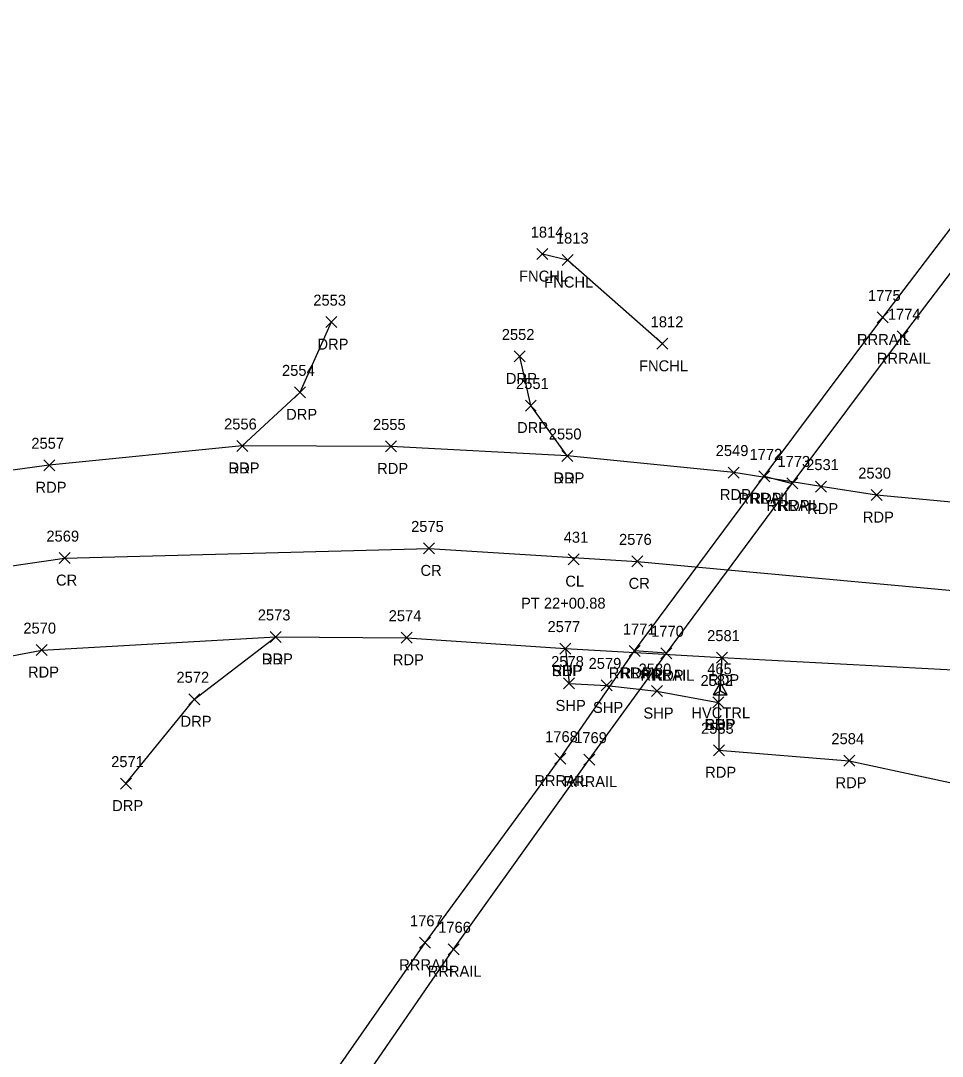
# Model space of a CAD drawing. Extents: x 1767353 to 1772625, y 740790 to 747702.
# Drawn here: x 1772120.9 to 1772288.6, y 747316.1 to 747504.6 of the extents above; entities that cross this region are included whole.
import ezdxf

# ---------------------------------------------------------------- set-up
doc = ezdxf.new("R2010")
doc.units = 0
for name, color, linetype in [('A_A', 7, 'Continuous'), ('A_C', 7, 'Continuous'), ('A_I', 7, 'Continuous'), ('A_TIC', 7, 'Continuous'), ('C_A', 7, 'Continuous'), ('C_I', 7, 'Continuous'), ('CPSM', 7, 'Continuous'), ('L_A', 7, 'Continuous'), ('L_I', 7, 'Continuous'), ('L_TIC', 7, 'Continuous'), ('LFNC', 7, 'Continuous'), ('P_A', 7, 'Continuous'), ('P_I', 7, 'Continuous'), ('P_TIC', 7, 'Continuous'), ('PET', 7, 'Continuous'), ('PRC', 7, 'Continuous'), ('PSP', 7, 'Continuous'), ('R_A', 7, 'Continuous'), ('R_I', 7, 'Continuous'), ('R_TIC', 7, 'Continuous'), ('RDP', 7, 'Continuous'), ('RR', 7, 'Continuous')]:
    doc.layers.add(name, color=color, linetype=linetype)

msp = doc.modelspace()

# ---------------------------------------------------------------- linework, layer by layer
at = {"layer": 'A_TIC'}
for points in [[(1772220.5, 747405.59), (1772222.5, 747407.59)], [(1772222.5, 747405.59), (1772220.5, 747407.59)]]:
    msp.add_lwpolyline(points, dxfattribs=at)
at = {"layer": 'CPSM'}
for p, q in [((1772246.97, 747381.92), (1772248.22, 747384.08)), ((1772249.47, 747381.92), (1772248.22, 747384.08)), ((1772248.22, 747382.64), (1772248.22, 747384.08)), ((1772246.97, 747381.92), (1772248.22, 747382.64)), ((1772246.97, 747381.92), (1772249.47, 747381.92)), ((1772248.22, 747382.64), (1772248.22, 747382.64)), ((1772248.22, 747382.64), (1772249.47, 747381.92))]:
    msp.add_line(p, q, dxfattribs=at)
at = {"layer": 'L_TIC'}
for points in [[(1772214.82, 747461.1), (1772216.82, 747463.1)], [(1772216.82, 747461.1), (1772214.82, 747463.1)], [(1772219.4, 747460.02), (1772221.4, 747462.02)], [(1772221.4, 747460.02), (1772219.4, 747462.02)], [(1772236.65, 747444.78), (1772238.65, 747446.78)], [(1772238.65, 747444.78), (1772236.65, 747446.78)]]:
    msp.add_lwpolyline(points, dxfattribs=at)
at = {"layer": 'LFNC'}
msp.add_lwpolyline([(1772237.65, 747445.78), (1772220.4, 747461.02), (1772215.82, 747462.1)], dxfattribs=at)
at = {"layer": 'P_TIC'}
for points in [[(1772160.2, 747426.19), (1772162.2, 747428.19)], [(1772162.2, 747426.19), (1772160.2, 747428.19)], [(1772187.24, 747426.11), (1772189.24, 747428.11)], [(1772189.24, 747426.11), (1772187.24, 747428.11)], [(1772219.33, 747424.37), (1772221.33, 747426.37)], [(1772221.33, 747424.37), (1772219.33, 747426.37)], [(1772125.06, 747422.68), (1772127.06, 747424.68)], [(1772127.06, 747422.68), (1772125.06, 747424.68)], [(1772249.63, 747421.36), (1772251.63, 747423.36)], [(1772251.63, 747421.36), (1772249.63, 747423.36)], [(1772255.2, 747420.67), (1772257.2, 747422.67)], [(1772257.2, 747420.67), (1772255.2, 747422.67)], [(1772260.28, 747419.38), (1772262.28, 747421.38)], [(1772262.28, 747419.38), (1772260.28, 747421.38)], [(1772265.51, 747418.8), (1772267.51, 747420.8)], [(1772267.51, 747418.8), (1772265.51, 747420.8)], [(1772275.65, 747417.25), (1772277.65, 747419.25)], [(1772277.65, 747417.25), (1772275.65, 747419.25)], [(1772194.18, 747407.55), (1772196.18, 747409.55)], [(1772196.18, 747407.55), (1772194.18, 747409.55)], [(1772127.86, 747405.79), (1772129.86, 747407.79)], [(1772129.86, 747405.79), (1772127.86, 747407.79)], [(1772232.07, 747405.2), (1772234.07, 747407.2)], [(1772234.07, 747405.2), (1772232.07, 747407.2)], [(1772166.27, 747391.45), (1772168.27, 747393.45)], [(1772168.27, 747391.45), (1772166.27, 747393.45)], [(1772190.1, 747391.31), (1772192.1, 747393.31)], [(1772192.1, 747391.31), (1772190.1, 747393.31)], [(1772123.7, 747389.05), (1772125.7, 747391.05)], [(1772125.7, 747389.05), (1772123.7, 747391.05)], [(1772219.01, 747389.33), (1772221.01, 747391.33)], [(1772221.01, 747389.33), (1772219.01, 747391.33)], [(1772219.01, 747389.33), (1772221.01, 747391.33)], [(1772221.01, 747389.33), (1772219.01, 747391.33)], [(1772231.59, 747388.89), (1772233.59, 747390.89)], [(1772233.59, 747388.89), (1772231.59, 747390.89)], [(1772237.38, 747388.48), (1772239.38, 747390.48)], [(1772239.38, 747388.48), (1772237.38, 747390.48)], [(1772247.49, 747387.68), (1772249.49, 747389.68)], [(1772249.49, 747387.68), (1772247.49, 747389.68)], [(1772247.49, 747387.68), (1772249.49, 747389.68)], [(1772249.49, 747387.68), (1772247.49, 747389.68)], [(1772219.67, 747382.98), (1772221.67, 747384.98)], [(1772221.67, 747382.98), (1772219.67, 747384.98)], [(1772226.49, 747382.63), (1772228.49, 747384.63)], [(1772228.49, 747382.63), (1772226.49, 747384.63)], [(1772235.67, 747381.6), (1772237.67, 747383.6)], [(1772237.67, 747381.6), (1772235.67, 747383.6)], [(1772246.85, 747379.52), (1772248.85, 747381.52)], [(1772248.85, 747379.52), (1772246.85, 747381.52)], [(1772246.85, 747379.52), (1772248.85, 747381.52)], [(1772248.85, 747379.52), (1772246.85, 747381.52)], [(1772246.94, 747370.83), (1772248.94, 747372.83)], [(1772248.94, 747370.83), (1772246.94, 747372.83)], [(1772270.67, 747368.93), (1772272.67, 747370.93)], [(1772272.67, 747368.93), (1772270.67, 747370.93)]]:
    msp.add_lwpolyline(points, dxfattribs=at)
at = {"layer": 'PET'}
for points in [[(1772376.42, 747407.07), (1772350, 747410.75), (1772301.95, 747415.87), (1772276.65, 747418.25), (1772266.51, 747419.8), (1772250.63, 747422.36), (1772220.33, 747425.37), (1772188.24, 747427.11), (1772161.2, 747427.19), (1772126.06, 747423.68), (1772087.39, 747418.44)], [(1772256.2, 747421.67), (1772261.28, 747420.38)], [(1772080.59, 747381.74), (1772124.7, 747390.05), (1772167.27, 747392.45), (1772191.1, 747392.31), (1772220.01, 747390.33), (1772248.49, 747388.68), (1772293.98, 747386.28), (1772309.1, 747385.27), (1772371.76, 747378.07), (1772423.02, 747369.36), (1772445.68, 747366.79)], [(1772238.38, 747389.48), (1772232.59, 747389.89)], [(1772248.49, 747388.68), (1772247.85, 747380.52), (1772247.94, 747371.83), (1772271.67, 747369.93), (1772298.73, 747364.09), (1772330.57, 747351.94), (1772345.39, 747340.22), (1772358.44, 747325.87), (1772369.01, 747310.86), (1772376.2, 747299.13), (1772388.77, 747279.71), (1772413.33, 747239.35), (1772432.47, 747203.55), (1772442.3, 747177.42), (1772448.21, 747146.38), (1772450.04, 747126.57), (1772447.64, 747094.15), (1772439.71, 747049.07), (1772429.11, 746997.48), (1772420.36, 746945.09), (1772413.46, 746884.56)]]:
    msp.add_lwpolyline(points, dxfattribs=at)
at = {"layer": 'PRC'}
msp.add_lwpolyline([(1772025.6, 747384.96), (1772051.83, 747392.67), (1772087.04, 747400.73), (1772128.86, 747406.79), (1772195.18, 747408.55), (1772233.07, 747406.2), (1772307.7, 747399.3), (1772391.16, 747389.23), (1772447.2, 747381.54)], dxfattribs=at)
at = {"layer": 'PSP'}
msp.add_lwpolyline([(1772220.01, 747390.33), (1772220.67, 747383.98), (1772227.49, 747383.63), (1772236.67, 747382.6), (1772247.85, 747380.52)], dxfattribs=at)
at = {"layer": 'R_TIC'}
for points in [[(1772276.77, 747449.57), (1772278.77, 747451.57)], [(1772278.77, 747449.57), (1772276.77, 747451.57)], [(1772176.38, 747448.72), (1772178.38, 747450.72)], [(1772178.38, 747448.72), (1772176.38, 747450.72)], [(1772280.38, 747446.15), (1772282.38, 747448.15)], [(1772282.38, 747446.15), (1772280.38, 747448.15)], [(1772210.68, 747442.48), (1772212.68, 747444.48)], [(1772212.68, 747442.48), (1772210.68, 747444.48)], [(1772170.68, 747435.95), (1772172.68, 747437.95)], [(1772172.68, 747435.95), (1772170.68, 747437.95)], [(1772212.71, 747433.55), (1772214.71, 747435.55)], [(1772214.71, 747433.55), (1772212.71, 747435.55)], [(1772160.2, 747426.19), (1772162.2, 747428.19)], [(1772162.2, 747426.19), (1772160.2, 747428.19)], [(1772219.33, 747424.37), (1772221.33, 747426.37)], [(1772221.33, 747424.37), (1772219.33, 747426.37)], [(1772255.2, 747420.67), (1772257.2, 747422.67)], [(1772257.2, 747420.67), (1772255.2, 747422.67)], [(1772260.28, 747419.38), (1772262.28, 747421.38)], [(1772262.28, 747419.38), (1772260.28, 747421.38)], [(1772166.27, 747391.45), (1772168.27, 747393.45)], [(1772168.27, 747391.45), (1772166.27, 747393.45)], [(1772231.59, 747388.89), (1772233.59, 747390.89)], [(1772233.59, 747388.89), (1772231.59, 747390.89)], [(1772237.38, 747388.48), (1772239.38, 747390.48)], [(1772239.38, 747388.48), (1772237.38, 747390.48)], [(1772151.47, 747380.1), (1772153.47, 747382.1)], [(1772153.47, 747380.1), (1772151.47, 747382.1)], [(1772218.05, 747369.3), (1772220.05, 747371.3)], [(1772220.05, 747369.3), (1772218.05, 747371.3)], [(1772223.35, 747369.12), (1772225.35, 747371.12)], [(1772225.35, 747369.12), (1772223.35, 747371.12)], [(1772139.02, 747364.76), (1772141.02, 747366.76)], [(1772141.02, 747364.76), (1772139.02, 747366.76)], [(1772193.46, 747335.8), (1772195.46, 747337.8)], [(1772195.46, 747335.8), (1772193.46, 747337.8)], [(1772198.65, 747334.62), (1772200.65, 747336.62)], [(1772200.65, 747334.62), (1772198.65, 747336.62)]]:
    msp.add_lwpolyline(points, dxfattribs=at)
at = {"layer": 'RDP'}
for points in [[(1772177.38, 747449.72), (1772171.68, 747436.95), (1772161.2, 747427.19)], [(1772220.33, 747425.37), (1772213.71, 747434.55), (1772211.68, 747443.48)], [(1772140.02, 747365.76), (1772152.47, 747381.1), (1772167.27, 747392.45)]]:
    msp.add_lwpolyline(points, dxfattribs=at)
at = {"layer": 'RR'}
for points in [[(1771960.76, 746895.46), (1771976.57, 746936.04), (1771991.76, 746972.7), (1772003.71, 747000.43), (1772025.97, 747048.7), (1772044.45, 747086.9), (1772066.42, 747128.97), (1772087.05, 747166.47), (1772110.84, 747207.58), (1772133.43, 747244.66), (1772156.72, 747281.04), (1772175.9, 747310.14), (1772194.46, 747336.8), (1772219.05, 747370.3), (1772232.59, 747389.89), (1772256.2, 747421.67), (1772277.77, 747450.57), (1772416.44, 747632.57), (1772465.26, 747696.66)], [(1771963.49, 746888.34), (1771980.41, 746932.18), (1771994.59, 746967.04), (1772007.72, 746997.13), (1772029.49, 747045.02), (1772048.72, 747084.09), (1772070.77, 747126.16), (1772091.38, 747163.68), (1772115.23, 747205.31), (1772138.09, 747242.79), (1772160.69, 747278.1), (1772180.23, 747307.44), (1772199.65, 747335.62), (1772224.35, 747370.12), (1772238.38, 747389.48), (1772261.28, 747420.38), (1772281.38, 747447.15), (1772420.28, 747629.6), (1772469.26, 747693.79)]]:
    msp.add_lwpolyline(points, dxfattribs=at)

# ---------------------------------------------------------------- texts
at = {"layer": 'A_A'}
msp.add_text('CL', height=2, dxfattribs=at).set_placement((1772219.99, 747401.59))
at = {"layer": 'A_C'}
msp.add_text('PT 22+00.88', height=2, dxfattribs=at).set_placement((1772211.92, 747397.59))
at = {"layer": 'A_I'}
msp.add_text('431', height=2, dxfattribs=at).set_placement((1772219.7, 747409.59))
at = {"layer": 'C_A'}
msp.add_text('HVCTRL', height=2, dxfattribs=at).set_placement((1772242.92, 747377.64))
at = {"layer": 'C_I'}
msp.add_text('465', height=2, dxfattribs=at).set_placement((1772245.82, 747385.64))
at = {"layer": 'L_A'}
for p in [(1772211.57, 747457.1), (1772216.15, 747456.02), (1772233.4, 747440.78)]:
    msp.add_text('FNCHL', height=2, dxfattribs=at).set_placement(p)
at = {"layer": 'L_I'}
for s, p in [('1814', (1772213.69, 747465.1)), ('1813', (1772218.27, 747464.02)), ('1812', (1772235.52, 747448.78))]:
    msp.add_text(s, height=2, dxfattribs=at).set_placement(p)
at = {"layer": 'P_A'}
for s, p in [('RDP', (1772158.68, 747422.19)), ('RDP', (1772185.73, 747422.11)), ('RDP', (1772217.81, 747420.37)), ('RDP', (1772123.55, 747418.68)), ('RDP', (1772248.11, 747417.36)), ('RDP', (1772253.69, 747416.67)), ('RDP', (1772258.77, 747415.38)), ('RDP', (1772264, 747414.8)), ('RDP', (1772274.14, 747413.25)), ('CR', (1772193.62, 747403.55)), ('CR', (1772127.29, 747401.79)), ('CR', (1772231.51, 747401.2)), ('RDP', (1772164.75, 747387.45)), ('RDP', (1772188.59, 747387.31)), ('SHP', (1772217.54, 747385.33)), ('RDP', (1772217.5, 747385.33)), ('RDP', (1772122.19, 747385.05)), ('RDP', (1772230.07, 747384.89)), ('RDP', (1772235.87, 747384.48)), ('RDP', (1772245.98, 747383.68)), ('RDP', (1772245.98, 747383.68)), ('SHP', (1772218.21, 747378.98)), ('SHP', (1772225.02, 747378.63)), ('SHP', (1772234.2, 747377.6)), ('SHP', (1772245.38, 747375.52)), ('RDP', (1772245.34, 747375.52)), ('RDP', (1772245.43, 747366.83)), ('RDP', (1772269.16, 747364.93))]:
    msp.add_text(s, height=2, dxfattribs=at).set_placement(p)
at = {"layer": 'P_I'}
for s, p in [('2556', (1772157.88, 747430.19)), ('2555', (1772184.98, 747430.11)), ('2557', (1772122.8, 747426.68)), ('2550', (1772216.98, 747428.37)), ('2549', (1772247.36, 747425.36)), ('1772', (1772253.51, 747424.67)), ('1773', (1772258.59, 747423.38)), ('2531', (1772263.82, 747422.8)), ('2530', (1772273.3, 747421.25)), ('2569', (1772125.54, 747409.79)), ('2575', (1772191.92, 747411.55)), ('2576', (1772229.76, 747409.2)), ('2573', (1772164.01, 747395.45)), ('2574', (1772187.84, 747395.31)), ('2570', (1772121.35, 747393.05)), ('2577', (1772216.75, 747393.33)), ('2577', (1772216.75, 747393.33)), ('1771', (1772230.46, 747392.89)), ('1770', (1772235.6, 747392.48)), ('2581', (1772245.8, 747391.68)), ('2581', (1772245.8, 747391.68)), ('2578', (1772217.41, 747386.98)), ('2579', (1772224.22, 747386.63)), ('2580', (1772233.32, 747385.6)), ('2582', (1772244.59, 747383.52)), ('2582', (1772244.59, 747383.52)), ('2583', (1772244.69, 747374.83)), ('2584', (1772268.41, 747372.93))]:
    msp.add_text(s, height=2, dxfattribs=at).set_placement(p)
at = {"layer": 'R_A'}
for s, p in [('RRRAIL', (1772273.06, 747445.57)), ('DRP', (1772174.87, 747444.72)), ('RRRAIL', (1772276.68, 747442.15)), ('DRP', (1772209.17, 747438.48)), ('DRP', (1772169.17, 747431.95)), ('DRP', (1772211.2, 747429.55)), ('DRP', (1772158.68, 747422.19)), ('DRP', (1772217.81, 747420.37)), ('RRRAIL', (1772251.49, 747416.67)), ('RRRAIL', (1772256.57, 747415.38)), ('DRP', (1772164.75, 747387.45)), ('RRRAIL', (1772227.88, 747384.89)), ('RRRAIL', (1772233.67, 747384.48)), ('DRP', (1772149.96, 747376.1)), ('RRRAIL', (1772214.34, 747365.3)), ('RRRAIL', (1772219.64, 747365.12)), ('DRP', (1772137.51, 747360.76)), ('RRRAIL', (1772189.75, 747331.8)), ('RRRAIL', (1772194.94, 747330.62))]:
    msp.add_text(s, height=2, dxfattribs=at).set_placement(p)
at = {"layer": 'R_I'}
for s, p in [('1775', (1772275.08, 747453.57)), ('2553', (1772174.12, 747452.72)), ('1774', (1772278.69, 747450.15)), ('2552', (1772208.42, 747446.48)), ('2554', (1772168.42, 747439.95)), ('2551', (1772211.02, 747437.55)), ('2556', (1772157.88, 747430.19)), ('2550', (1772216.98, 747428.37)), ('1772', (1772253.51, 747424.67)), ('1773', (1772258.59, 747423.38)), ('2573', (1772164.01, 747395.45)), ('1771', (1772230.46, 747392.89)), ('1770', (1772235.6, 747392.48)), ('2572', (1772149.21, 747384.1)), ('1768', (1772216.31, 747373.3)), ('1769', (1772221.6, 747373.12)), ('2571', (1772137.33, 747368.76)), ('1767', (1772191.72, 747339.8)), ('1766', (1772196.85, 747338.62))]:
    msp.add_text(s, height=2, dxfattribs=at).set_placement(p)

doc.saveas('drawing.dxf')
